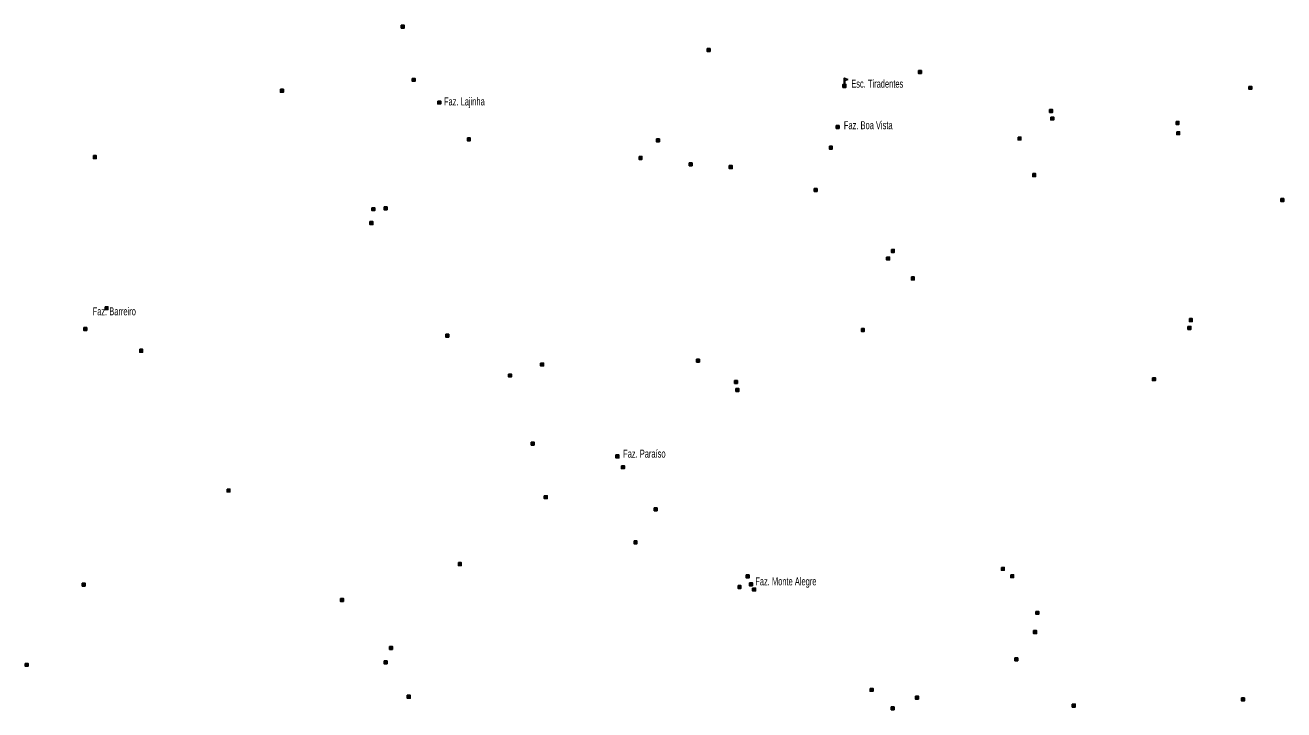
# Model space of a CAD drawing. Extents: x 447.8 to 473.9, y 7733.1 to 7760.8.
# Drawn here: x 448.25 to 460.83, y 7747.01 to 7753.85 of the extents above; entities that cross this region are included whole.
import ezdxf

# ---------------------------------------------------------------- set-up
doc = ezdxf.new("R2010")
doc.units = 0
doc.header["$LTSCALE"] = 0.032
doc.layers.add('2', color=7, linetype='Continuous', lineweight=25)
doc.layers.add('4', color=7, linetype='Continuous', lineweight=25)
doc.layers.add('61', color=7, linetype='Continuous')

msp = doc.modelspace()

# ---------------------------------------------------------------- hatches: boundary and pattern name
at = {"layer": '2'}
for points in [[(452.0112, 7753.848), (452.0402, 7753.848), (452.0402, 7753.819), (452.0112, 7753.819)], [(455.0678, 7753.6141), (455.0968, 7753.6141), (455.0968, 7753.5851), (455.0678, 7753.5851)], [(452.1197, 7753.3165), (452.1487, 7753.3165), (452.1487, 7753.2875), (452.1197, 7753.2875)], [(457.1804, 7753.3943), (457.2094, 7753.3943), (457.2094, 7753.3653), (457.1804, 7753.3653)], [(450.8034, 7753.2073), (450.8324, 7753.2073), (450.8324, 7753.1783), (450.8034, 7753.1783)], [(460.4832, 7753.2364), (460.5122, 7753.2364), (460.5122, 7753.2074), (460.4832, 7753.2074)], [(452.3761, 7753.0899), (452.4051, 7753.0899), (452.4051, 7753.0609), (452.3761, 7753.0609)], [(458.4919, 7753.0052), (458.5209, 7753.0052), (458.5209, 7752.9762), (458.4919, 7752.9762)], [(458.5033, 7752.9297), (458.5323, 7752.9297), (458.5323, 7752.9007), (458.5033, 7752.9007)], [(456.3587, 7752.845), (456.3877, 7752.845), (456.3877, 7752.816), (456.3587, 7752.816)], [(459.7553, 7752.8862), (459.7843, 7752.8862), (459.7843, 7752.8572), (459.7553, 7752.8572)], [(452.6713, 7752.7214), (452.7003, 7752.7214), (452.7003, 7752.6924), (452.6713, 7752.6924)], [(454.5619, 7752.7122), (454.5909, 7752.7122), (454.5909, 7752.6832), (454.5619, 7752.6832)], [(458.176, 7752.7306), (458.205, 7752.7306), (458.205, 7752.7016), (458.176, 7752.7016)], [(459.7622, 7752.7832), (459.7912, 7752.7832), (459.7912, 7752.7542), (459.7622, 7752.7542)], [(448.933, 7752.5448), (448.962, 7752.5448), (448.962, 7752.5158), (448.933, 7752.5158)], [(454.388, 7752.536), (454.417, 7752.536), (454.417, 7752.507), (454.388, 7752.507)], [(456.29, 7752.639), (456.319, 7752.639), (456.319, 7752.61), (456.29, 7752.61)], [(454.8892, 7752.4719), (454.9182, 7752.4719), (454.9182, 7752.4429), (454.8892, 7752.4429)], [(455.2898, 7752.4445), (455.3188, 7752.4445), (455.3188, 7752.4155), (455.2898, 7752.4155)], [(458.3225, 7752.3643), (458.3515, 7752.3643), (458.3515, 7752.3353), (458.3225, 7752.3353)], [(456.1389, 7752.2156), (456.1679, 7752.2156), (456.1679, 7752.1866), (456.1389, 7752.1866)], [(451.8394, 7752.0322), (451.8684, 7752.0322), (451.8684, 7752.0032), (451.8394, 7752.0032)], [(460.8036, 7752.1149), (460.8326, 7752.1149), (460.8326, 7752.0859), (460.8036, 7752.0859)], [(451.7167, 7752.024), (451.7457, 7752.024), (451.7457, 7751.995), (451.7167, 7751.995)], [(451.6976, 7751.885), (451.7266, 7751.885), (451.7266, 7751.856), (451.6976, 7751.856)], [(456.8622, 7751.5312), (456.8912, 7751.5312), (456.8912, 7751.5022), (456.8622, 7751.5022)], [(456.9103, 7751.6067), (456.9393, 7751.6067), (456.9393, 7751.5777), (456.9103, 7751.5777)], [(457.1094, 7751.3321), (457.1384, 7751.3321), (457.1384, 7751.3031), (457.1094, 7751.3031)], [(449.0503, 7751.0344), (449.0793, 7751.0344), (449.0793, 7751.0054), (449.0503, 7751.0054)], [(459.8881, 7750.9155), (459.9171, 7750.9155), (459.9171, 7750.8865), (459.8881, 7750.8865)], [(448.8376, 7750.8271), (448.8666, 7750.8271), (448.8666, 7750.7981), (448.8376, 7750.7981)], [(456.6104, 7750.8171), (456.6394, 7750.8171), (456.6394, 7750.7881), (456.6104, 7750.7881)], [(459.8744, 7750.8377), (459.9034, 7750.8377), (459.9034, 7750.8087), (459.8744, 7750.8087)], [(452.4562, 7750.7599), (452.4852, 7750.7599), (452.4852, 7750.7309), (452.4562, 7750.7309)], [(449.3965, 7750.609), (449.4255, 7750.609), (449.4255, 7750.58), (449.3965, 7750.58)], [(453.4038, 7750.4715), (453.4328, 7750.4715), (453.4328, 7750.4425), (453.4038, 7750.4425)], [(454.9625, 7750.5104), (454.9915, 7750.5104), (454.9915, 7750.4814), (454.9625, 7750.4814)], [(453.0833, 7750.3616), (453.1123, 7750.3616), (453.1123, 7750.3326), (453.0833, 7750.3326)], [(455.3424, 7750.2975), (455.3714, 7750.2975), (455.3714, 7750.2685), (455.3424, 7750.2685)], [(459.5196, 7750.325), (459.5486, 7750.325), (459.5486, 7750.296), (459.5196, 7750.296)], [(455.3562, 7750.2174), (455.3852, 7750.2174), (455.3852, 7750.1884), (455.3562, 7750.1884)], [(453.3099, 7749.6818), (453.3389, 7749.6818), (453.3389, 7749.6528), (453.3099, 7749.6528)], [(454.1568, 7749.5536), (454.1858, 7749.5536), (454.1858, 7749.5246), (454.1568, 7749.5246)], [(454.2117, 7749.4461), (454.2407, 7749.4461), (454.2407, 7749.4171), (454.2117, 7749.4171)], [(450.269, 7749.2131), (450.298, 7749.2131), (450.298, 7749.1841), (450.269, 7749.1841)], [(453.4404, 7749.1462), (453.4694, 7749.1462), (453.4694, 7749.1172), (453.4404, 7749.1172)], [(454.539, 7749.0249), (454.568, 7749.0249), (454.568, 7748.9959), (454.539, 7748.9959)], [(454.3376, 7748.6953), (454.3666, 7748.6953), (454.3666, 7748.6663), (454.3376, 7748.6663)], [(452.5821, 7748.4779), (452.6111, 7748.4779), (452.6111, 7748.4489), (452.5821, 7748.4489)], [(458.0089, 7748.4298), (458.0379, 7748.4298), (458.0379, 7748.4008), (458.0089, 7748.4008)], [(448.8213, 7748.2725), (448.8503, 7748.2725), (448.8503, 7748.2435), (448.8213, 7748.2435)], [(455.4592, 7748.3543), (455.4882, 7748.3543), (455.4882, 7748.3253), (455.4592, 7748.3253)], [(455.4912, 7748.2764), (455.5202, 7748.2764), (455.5202, 7748.2474), (455.4912, 7748.2474)], [(458.1028, 7748.3566), (458.1318, 7748.3566), (458.1318, 7748.3276), (458.1028, 7748.3276)], [(455.3768, 7748.249), (455.4058, 7748.249), (455.4058, 7748.22), (455.3768, 7748.22)], [(455.5232, 7748.2238), (455.5522, 7748.2238), (455.5522, 7748.1948), (455.5232, 7748.1948)], [(451.4032, 7748.1198), (451.4322, 7748.1198), (451.4322, 7748.0908), (451.4032, 7748.0908)], [(458.3546, 7747.9903), (458.3836, 7747.9903), (458.3836, 7747.9613), (458.3546, 7747.9613)], [(458.3317, 7747.7981), (458.3607, 7747.7981), (458.3607, 7747.7691), (458.3317, 7747.7691)], [(451.8939, 7747.64), (451.9229, 7747.64), (451.9229, 7747.611), (451.8939, 7747.611)], [(458.144, 7747.5257), (458.173, 7747.5257), (458.173, 7747.4967), (458.144, 7747.4967)], [(448.2514, 7747.4709), (448.2804, 7747.4709), (448.2804, 7747.4419), (448.2514, 7747.4419)], [(451.8394, 7747.4955), (451.8684, 7747.4955), (451.8684, 7747.4665), (451.8394, 7747.4665)], [(452.0711, 7747.1519), (452.1001, 7747.1519), (452.1001, 7747.1229), (452.0711, 7747.1229)], [(456.6974, 7747.2213), (456.7264, 7747.2213), (456.7264, 7747.1923), (456.6974, 7747.1923)], [(457.1506, 7747.1435), (457.1796, 7747.1435), (457.1796, 7747.1145), (457.1506, 7747.1145)], [(456.908, 7747.0359), (456.937, 7747.0359), (456.937, 7747.0069), (456.908, 7747.0069)], [(458.7185, 7747.0634), (458.7475, 7747.0634), (458.7475, 7747.0344), (458.7185, 7747.0344)], [(460.4099, 7747.1252), (460.4389, 7747.1252), (460.4389, 7747.0962), (460.4099, 7747.0962)]]:
    msp.add_hatch(color=256, dxfattribs=at).paths.add_polyline_path(points)
at = {"layer": '4'}
msp.add_hatch(color=256, dxfattribs=at).paths.add_polyline_path([(456.426, 7753.2263), (456.426, 7753.2563), (456.456, 7753.2563), (456.456, 7753.2263)])

# ---------------------------------------------------------------- linework, layer by layer
at = {"layer": '2'}
for points in [[(452.0112, 7753.848), (452.0402, 7753.848), (452.0402, 7753.819), (452.0112, 7753.819)], [(455.0678, 7753.6141), (455.0968, 7753.6141), (455.0968, 7753.5851), (455.0678, 7753.5851)], [(452.1197, 7753.3165), (452.1487, 7753.3165), (452.1487, 7753.2875), (452.1197, 7753.2875)], [(457.1804, 7753.3943), (457.2094, 7753.3943), (457.2094, 7753.3653), (457.1804, 7753.3653)], [(450.8034, 7753.2073), (450.8324, 7753.2073), (450.8324, 7753.1783), (450.8034, 7753.1783)], [(460.4832, 7753.2364), (460.5122, 7753.2364), (460.5122, 7753.2074), (460.4832, 7753.2074)], [(452.3761, 7753.0899), (452.4051, 7753.0899), (452.4051, 7753.0609), (452.3761, 7753.0609)], [(458.4919, 7753.0052), (458.5209, 7753.0052), (458.5209, 7752.9762), (458.4919, 7752.9762)], [(458.5033, 7752.9297), (458.5323, 7752.9297), (458.5323, 7752.9007), (458.5033, 7752.9007)], [(456.3587, 7752.845), (456.3877, 7752.845), (456.3877, 7752.816), (456.3587, 7752.816)], [(459.7553, 7752.8862), (459.7843, 7752.8862), (459.7843, 7752.8572), (459.7553, 7752.8572)], [(452.6713, 7752.7214), (452.7003, 7752.7214), (452.7003, 7752.6924), (452.6713, 7752.6924)], [(454.5619, 7752.7122), (454.5909, 7752.7122), (454.5909, 7752.6832), (454.5619, 7752.6832)], [(458.176, 7752.7306), (458.205, 7752.7306), (458.205, 7752.7016), (458.176, 7752.7016)], [(459.7622, 7752.7832), (459.7912, 7752.7832), (459.7912, 7752.7542), (459.7622, 7752.7542)], [(448.933, 7752.5448), (448.962, 7752.5448), (448.962, 7752.5158), (448.933, 7752.5158)], [(454.388, 7752.536), (454.417, 7752.536), (454.417, 7752.507), (454.388, 7752.507)], [(456.29, 7752.639), (456.319, 7752.639), (456.319, 7752.61), (456.29, 7752.61)], [(454.8892, 7752.4719), (454.9182, 7752.4719), (454.9182, 7752.4429), (454.8892, 7752.4429)], [(455.2898, 7752.4445), (455.3188, 7752.4445), (455.3188, 7752.4155), (455.2898, 7752.4155)], [(458.3225, 7752.3643), (458.3515, 7752.3643), (458.3515, 7752.3353), (458.3225, 7752.3353)], [(456.1389, 7752.2156), (456.1679, 7752.2156), (456.1679, 7752.1866), (456.1389, 7752.1866)], [(451.8394, 7752.0322), (451.8684, 7752.0322), (451.8684, 7752.0032), (451.8394, 7752.0032)], [(460.8036, 7752.1149), (460.8326, 7752.1149), (460.8326, 7752.0859), (460.8036, 7752.0859)], [(451.7167, 7752.024), (451.7457, 7752.024), (451.7457, 7751.995), (451.7167, 7751.995)], [(451.6976, 7751.885), (451.7266, 7751.885), (451.7266, 7751.856), (451.6976, 7751.856)], [(456.8622, 7751.5312), (456.8912, 7751.5312), (456.8912, 7751.5022), (456.8622, 7751.5022)], [(456.9103, 7751.6067), (456.9393, 7751.6067), (456.9393, 7751.5777), (456.9103, 7751.5777)], [(457.1094, 7751.3321), (457.1384, 7751.3321), (457.1384, 7751.3031), (457.1094, 7751.3031)], [(449.0503, 7751.0344), (449.0793, 7751.0344), (449.0793, 7751.0054), (449.0503, 7751.0054)], [(459.8881, 7750.9155), (459.9171, 7750.9155), (459.9171, 7750.8865), (459.8881, 7750.8865)], [(448.8376, 7750.8271), (448.8666, 7750.8271), (448.8666, 7750.7981), (448.8376, 7750.7981)], [(456.6104, 7750.8171), (456.6394, 7750.8171), (456.6394, 7750.7881), (456.6104, 7750.7881)], [(459.8744, 7750.8377), (459.9034, 7750.8377), (459.9034, 7750.8087), (459.8744, 7750.8087)], [(452.4562, 7750.7599), (452.4852, 7750.7599), (452.4852, 7750.7309), (452.4562, 7750.7309)], [(449.3965, 7750.609), (449.4255, 7750.609), (449.4255, 7750.58), (449.3965, 7750.58)], [(453.4038, 7750.4715), (453.4328, 7750.4715), (453.4328, 7750.4425), (453.4038, 7750.4425)], [(454.9625, 7750.5104), (454.9915, 7750.5104), (454.9915, 7750.4814), (454.9625, 7750.4814)], [(453.0833, 7750.3616), (453.1123, 7750.3616), (453.1123, 7750.3326), (453.0833, 7750.3326)], [(455.3424, 7750.2975), (455.3714, 7750.2975), (455.3714, 7750.2685), (455.3424, 7750.2685)], [(459.5196, 7750.325), (459.5486, 7750.325), (459.5486, 7750.296), (459.5196, 7750.296)], [(455.3562, 7750.2174), (455.3852, 7750.2174), (455.3852, 7750.1884), (455.3562, 7750.1884)], [(453.3099, 7749.6818), (453.3389, 7749.6818), (453.3389, 7749.6528), (453.3099, 7749.6528)], [(454.1568, 7749.5536), (454.1858, 7749.5536), (454.1858, 7749.5246), (454.1568, 7749.5246)], [(454.2117, 7749.4461), (454.2407, 7749.4461), (454.2407, 7749.4171), (454.2117, 7749.4171)], [(450.269, 7749.2131), (450.298, 7749.2131), (450.298, 7749.1841), (450.269, 7749.1841)], [(453.4404, 7749.1462), (453.4694, 7749.1462), (453.4694, 7749.1172), (453.4404, 7749.1172)], [(454.539, 7749.0249), (454.568, 7749.0249), (454.568, 7748.9959), (454.539, 7748.9959)], [(454.3376, 7748.6953), (454.3666, 7748.6953), (454.3666, 7748.6663), (454.3376, 7748.6663)], [(452.5821, 7748.4779), (452.6111, 7748.4779), (452.6111, 7748.4489), (452.5821, 7748.4489)], [(458.0089, 7748.4298), (458.0379, 7748.4298), (458.0379, 7748.4008), (458.0089, 7748.4008)], [(448.8213, 7748.2725), (448.8503, 7748.2725), (448.8503, 7748.2435), (448.8213, 7748.2435)], [(455.4592, 7748.3543), (455.4882, 7748.3543), (455.4882, 7748.3253), (455.4592, 7748.3253)], [(455.4912, 7748.2764), (455.5202, 7748.2764), (455.5202, 7748.2474), (455.4912, 7748.2474)], [(458.1028, 7748.3566), (458.1318, 7748.3566), (458.1318, 7748.3276), (458.1028, 7748.3276)], [(455.3768, 7748.249), (455.4058, 7748.249), (455.4058, 7748.22), (455.3768, 7748.22)], [(455.5232, 7748.2238), (455.5522, 7748.2238), (455.5522, 7748.1948), (455.5232, 7748.1948)], [(451.4032, 7748.1198), (451.4322, 7748.1198), (451.4322, 7748.0908), (451.4032, 7748.0908)], [(458.3546, 7747.9903), (458.3836, 7747.9903), (458.3836, 7747.9613), (458.3546, 7747.9613)], [(458.3317, 7747.7981), (458.3607, 7747.7981), (458.3607, 7747.7691), (458.3317, 7747.7691)], [(451.8939, 7747.64), (451.9229, 7747.64), (451.9229, 7747.611), (451.8939, 7747.611)], [(458.144, 7747.5257), (458.173, 7747.5257), (458.173, 7747.4967), (458.144, 7747.4967)], [(448.2514, 7747.4709), (448.2804, 7747.4709), (448.2804, 7747.4419), (448.2514, 7747.4419)], [(451.8394, 7747.4955), (451.8684, 7747.4955), (451.8684, 7747.4665), (451.8394, 7747.4665)], [(452.0711, 7747.1519), (452.1001, 7747.1519), (452.1001, 7747.1229), (452.0711, 7747.1229)], [(456.6974, 7747.2213), (456.7264, 7747.2213), (456.7264, 7747.1923), (456.6974, 7747.1923)], [(457.1506, 7747.1435), (457.1796, 7747.1435), (457.1796, 7747.1145), (457.1506, 7747.1145)], [(456.908, 7747.0359), (456.937, 7747.0359), (456.937, 7747.0069), (456.908, 7747.0069)], [(458.7185, 7747.0634), (458.7475, 7747.0634), (458.7475, 7747.0344), (458.7185, 7747.0344)], [(460.4099, 7747.1252), (460.4389, 7747.1252), (460.4389, 7747.0962), (460.4099, 7747.0962)]]:
    msp.add_lwpolyline(points, close=True, dxfattribs=at)
at = {"layer": '4'}
msp.add_line((456.4385, 7753.2563), (456.4435, 7753.2563), dxfattribs=at)
for points in [[(456.4385, 7753.2563), (456.4385, 7753.3188), (456.4735, 7753.3063), (456.4435, 7753.2958), (456.4435, 7753.2563)], [(456.426, 7753.2263), (456.426, 7753.2563), (456.456, 7753.2563), (456.456, 7753.2263)]]:
    msp.add_lwpolyline(points, close=True, dxfattribs=at)

# ---------------------------------------------------------------- texts
at = {"layer": '61', "width": 0.7}
for s, p in [('Esc. Tiradentes', (456.5086, 7753.2232)), ('Faz. Lajinha', (452.4375, 7753.046)), ('Faz. Boa Vista', (456.435, 7752.8087)), ('Faz. Barreiro', (448.9254, 7750.9487)), ('Faz. Paraíso', (454.2283, 7749.5265)), ('Faz. Monte Alegre', (455.5492, 7748.2506))]:
    msp.add_text(s, height=0.08, dxfattribs=at).set_placement(p)

doc.saveas('drawing.dxf')
